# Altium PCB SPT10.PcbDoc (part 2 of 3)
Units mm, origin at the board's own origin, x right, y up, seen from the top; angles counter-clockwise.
Board outline 194 x 91 mm, 4 copper layers (Top Layer, Mid-Layer 8, Mid-Layer 28, Bottom Layer); 266 components, 1 nets, 803 pads, 630 vias.
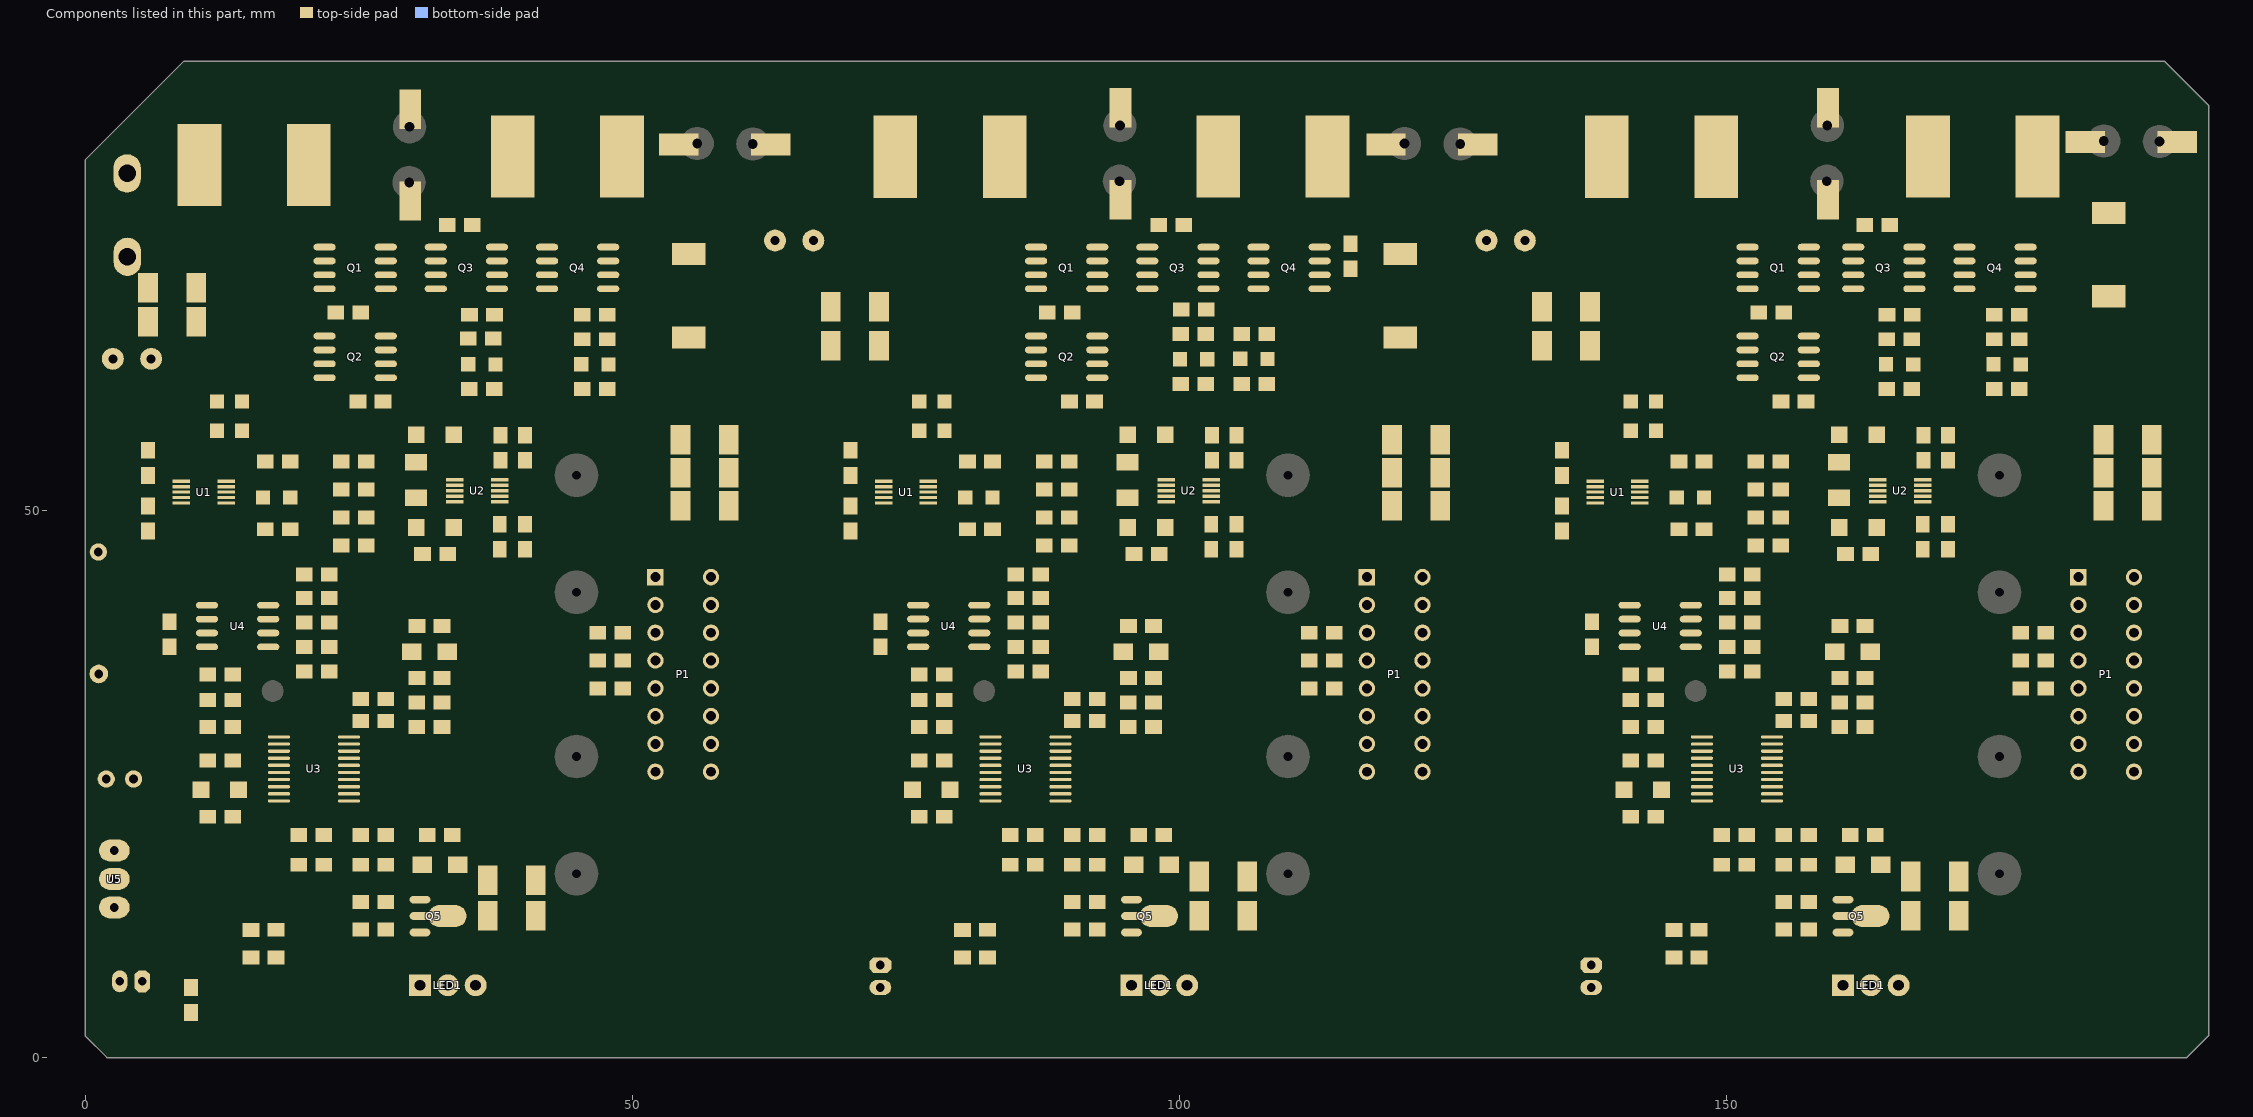
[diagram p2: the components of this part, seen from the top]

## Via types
v1: diameter 1, hole 0.5, Top Layer to Bottom Layer, 627 vias
v2: diameter 1, hole 0.5, Top Layer to Bottom Layer, tented top, 3 vias

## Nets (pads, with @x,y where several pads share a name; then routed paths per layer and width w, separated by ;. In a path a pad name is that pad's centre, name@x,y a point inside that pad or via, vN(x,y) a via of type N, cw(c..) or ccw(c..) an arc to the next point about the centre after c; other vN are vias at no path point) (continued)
copper on no net: | length 4395.1
  Top Layer w0.254: 5.764,64.758 5.764,62.742 6.458,62.742 7.27,61.93 7.27,52.53 7.646,52.154 8.795,52.154 ; 5.765,48.101 6.791,48.101 7.11,48.42 8.38,48.42 ; 5.773,51.657 8.795,51.657 ; 7.709,39.801 v1@7.709,41.549 ; 8.314,50.657 8.795,50.657 ; 8.795,51.157 10.083,51.157 10.57,50.67 10.57,47.56 11.338,46.792 23.414,46.792 ; 8.795,52.657 7.983,52.657 7.9,52.74 7.9,62.55 9.955,64.605 ; 9.44,64.974 9.44,68.53 ; 12.895,51.157 16.38,51.157 ; 12.895,51.657 14.027,51.657 15.25,52.88 18.747,52.88 ; 16.331,51.38 16.4,51.157 16.38,51.157 ; 16.38,51.332 16.38,51.157 ; 17.517,29.291 v1@17.517,30.323 ; 22.31,39.711 21.163,40.858 21.163,43.123 22.31,44.27 ; 30.25,51.15 31.376,52.276 33.79,52.276 ; 30.25,54.37 31.844,52.776 33.79,52.776 ; 30.84,46 31.89,47.05 34.95,47.05 35.69,47.79 35.69,51.11 36.856,52.276 37.89,52.276 ; 33.126,46.001 34.671,46.001 36.28,47.61 36.28,50.32 36.736,50.776 37.89,50.776 ; 33.679,48.43 34.89,48.43 35.14,48.68 35.14,51.276 ; 33.79,51.276 35.14,51.276 ; 33.79,51.776 34.753,51.776 35.3,52.324 35.3,61.069 ; 37.89,51.276 39.694,51.276 40.209,50.761 40.209,48.716 ; 37.89,51.776 39.616,51.776 40.211,52.371 40.211,54.57 ; 37.89,52.776 36.884,52.776 36.55,53.11 36.55,57.497 40.122,61.069 45.412,61.069 ; 39.29,69.74 39.29,60.95 35.94,57.6 35.94,52.076 35.14,51.276 ; 47.535,30.885 48.74,30.885 50.975,28.65 52.11,28.65 ; 68.205,61.835 70.78,61.835 71.5,61.115 71.5,52.46 71.806,52.154 72.955,52.154 ; 69.925,48.101 70.951,48.101 71.3,48.45 71.3,49.97 71.987,50.657 72.955,50.657 ; 69.933,51.657 72.955,51.657 ; 72.58,52.694 72.58,81.876 74.016,83.312 ; 72.677,39.803 v1@72.677,41.551 ; 72.955,51.157 74.243,51.157 74.73,50.67 74.73,47.56 75.498,46.792 87.624,46.792 ; 77.055,51.157 80.54,51.157 ; 77.055,51.657 78.187,51.657 79.41,52.88 82.907,52.88 ; 80.113,48.686 80.54,48.26 ; 80.185,54.445 80.621,54.445 ; 82.517,29.291 v1@82.517,30.323 ; 87.31,39.711 86.163,40.858 86.163,43.123 87.31,44.27 ; 95.25,51.15 96.376,52.276 98.79,52.276 ; 95.25,54.37 96.844,52.776 98.79,52.776 ; 95.84,46 96.89,47.05 99.95,47.05 100.69,47.79 100.69,51.11 101.856,52.276 102.89,52.276 ; 98.126,46.001 99.871,46.001 101.28,47.41 101.28,50.32 101.736,50.776 102.89,50.776 ; 98.679,48.43 99.84,48.43 100.14,48.73 100.14,51.276 ; 98.79,51.276 100.14,51.276 ; 98.79,51.776 99.746,51.776 100.106,52.136 100.106,61.54 ; 102.89,51.276 104.694,51.276 105.209,50.761 105.209,48.716 ; 102.89,51.776 104.616,51.776 105.211,52.371 105.211,54.57 ; 102.89,52.776 101.884,52.776 101.49,53.17 101.49,57.51 104.08,60.1 106.516,60.1 107.958,61.542 ; 103.93,69.74 103.93,60.78 100.96,57.81 100.96,52.096 100.14,51.276 ; 112.535,30.885 113.74,30.885 115.975,28.65 117.11,28.65 ; 133.76,61.99 135.96,61.99 136.5,61.45 136.5,52.46 136.806,52.154 137.955,52.154 ; 134.925,48.101 135.951,48.101 136.3,48.45 136.3,49.97 136.987,50.657 137.955,50.657 ; 134.933,51.657 137.955,51.657 ; 137.58,52.694 137.58,81.876 ; 137.677,39.803 v1@137.677,41.551 ; 137.955,51.157 139.243,51.157 139.73,50.67 139.73,47.56 140.498,46.792 152.624,46.792 ; 140.883,50.657 142.055,50.657 ; 142.055,51.157 145.54,51.157 ; 142.055,51.657 143.187,51.657 144.41,52.88 147.907,52.88 ; 145.113,48.686 145.54,48.26 ; 145.185,54.445 145.621,54.445 ; 147.517,29.291 v1@147.517,30.323 ; 147.907,54.446 148.333,54.02 ; 152.31,39.711 151.163,40.858 151.163,43.123 152.31,44.27 ; 160.25,51.15 161.376,52.276 163.79,52.276 ; 160.25,54.37 161.844,52.776 163.79,52.776 ; 160.84,46 161.89,47.05 164.95,47.05 165.69,47.79 165.69,51.11 166.856,52.276 167.89,52.276 ; 163.126,46.001 164.881,46.001 166.28,47.4 166.28,50.32 166.736,50.776 167.89,50.776 ; 163.679,48.43 164.89,48.43 165.14,48.68 165.14,51.276 ; 163.79,51.276 165.14,51.276 ; 163.79,51.782 164.927,51.782 165.32,52.175 165.32,58.9 164.6,59.62 164.6,61.07 ; 167.89,51.276 169.694,51.276 170.209,50.761 170.209,48.716 ; 167.89,51.776 169.616,51.776 170.211,52.371 170.211,54.57 ; 167.89,52.776 166.884,52.776 166.55,53.11 166.55,57.67 169.95,61.07 174.42,61.07 ; 168.86,60.72 165.92,57.78 165.92,52.056 165.14,51.276 ; 168.87,60.72 168.87,69.74 ; 177.535,30.885 178.74,30.885 180.975,28.65 182.11,28.65
  Top Layer w0.3: 12.062,57.262 11.11,56.31 11.11,52.51 11.463,52.157 12.895,52.157 ; 12.062,59.943 10.52,58.401 10.52,51.86 11.723,50.657 12.895,50.657 ; 13.21,27.42 13.51,27.12 ; 13.24,52.714 13.24,61.2 ; 13.51,22 14.52,22 16.611,24.091 17.009,24.091 ; 13.51,27.341 17.517,27.341 ; 13.51,30.21 15.729,27.991 17.717,27.991 19.351,27.991 21.36,30 ; 14.02,24.741 17.517,24.741 ; 17.14,33.48 15.61,31.95 15.61,29.51 16.479,28.641 17.717,28.641 ; 17.517,25.391 19.479,25.391 v1(19.99,24.88) ; 17.717,23.441 16.881,23.441 16.42,22.98 16.42,14.73 16.926,14.224 25.192,14.224 ; 17.717,26.041 v1(21.429,26.041) ; 17.717,26.691 19.531,26.691 v1(19.91,27.07) ; 19.526,22.367 22.55,25.391 24.117,25.391 ; 24.117,23.441 29.389,23.441 30.61,22.22 v1(30.61,22.29) ; 24.117,24.091 33.949,24.091 v1(35.75,22.29) ; 24.117,24.741 36.001,24.741 v1(37.31,26.05) ; 24.117,26.041 35.271,26.041 42.959,33.729 46.846,33.729 ; 24.117,26.691 34.841,26.691 44.419,36.269 46.844,36.269 ; 24.117,27.341 34.371,27.341 45.839,38.809 46.844,38.809 ; 24.117,27.991 33.951,27.991 46.04,40.08 53.225,40.08 ; 24.117,28.641 28.751,28.641 30.32,30.21 ; 24.117,29.291 25.091,29.291 25.19,29.39 25.19,30.74 ; 53.225,40.09 57.117,36.198 ; 76.222,57.262 75.27,56.31 75.27,52.51 75.623,52.157 77.055,52.157 ; 76.222,59.943 74.68,58.401 74.68,51.86 75.883,50.657 77.055,50.657 ; 77.4,52.714 77.4,61.36 ; 78.51,22 79.52,22 81.611,24.091 82.009,24.091 ; 78.51,27.341 82.517,27.341 ; 78.51,30.21 80.729,27.991 82.717,27.991 84.271,27.991 ; 79.02,24.741 82.517,24.741 ; 81.229,27.341 82.717,27.341 ; 82.14,33.48 80.61,31.95 80.61,29.51 81.479,28.641 82.717,28.641 ; 82.517,25.391 84.479,25.391 v1(84.99,24.88) ; 82.717,23.441 81.881,23.441 81.42,22.98 81.42,14.68 81.876,14.224 90.192,14.224 ; 82.717,26.041 v1(86.429,26.041) ; 82.717,26.691 84.531,26.691 v1(84.91,27.07) ; 84.351,27.991 86.36,30 ; 84.526,22.367 87.55,25.391 89.117,25.391 ; 89.117,23.441 94.389,23.441 v1@95.61,22.22 ; 89.117,24.091 98.949,24.091 v1(100.75,22.29) ; 89.117,24.741 101.001,24.741 v1(102.31,26.05) ; 89.117,26.041 100.271,26.041 107.959,33.729 111.846,33.729 ; 89.117,26.691 99.841,26.691 109.419,36.269 111.846,36.269 ; 89.117,27.341 99.371,27.341 110.839,38.809 112.069,38.809 ; 89.117,27.991 98.961,27.991 111.06,40.09 118.225,40.09 122.118,36.198 ; 89.117,28.641 93.751,28.641 95.32,30.21 ; 89.117,29.291 90.091,29.291 90.19,29.39 90.19,30.74 ; 140.883,50.657 139.68,51.86 139.68,58.401 141.222,59.943 ; 141.222,57.262 140.27,56.31 140.27,52.51 140.623,52.157 142.055,52.157 ; 142.4,52.714 142.4,61.36 ; 143.51,22 144.52,22 146.611,24.091 147.009,24.091 ; 143.51,27.341 147.517,27.341 ; 143.51,30.21 145.729,27.991 147.717,27.991 149.271,27.991 ; 144.02,24.741 147.517,24.741 ; 147.14,33.48 145.62,31.96 145.62,31.94 145.61,31.93 145.61,29.51 146.479,28.641 147.717,28.641 ; 147.517,25.391 149.479,25.391 v1(149.99,24.88) ; 147.717,23.441 146.881,23.441 146.49,23.05 146.49,14.75 147.016,14.224 155.192,14.224 ; 147.717,26.041 v1(151.429,26.041) ; 147.717,26.691 149.531,26.691 v1(149.91,27.07) ; 149.351,27.991 151.36,30 ; 149.526,22.367 152.55,25.391 154.117,25.391 ; 154.117,23.441 159.389,23.441 v1@160.61,22.22 ; 154.117,24.091 163.949,24.091 v1(165.75,22.29) ; 154.117,24.741 166.001,24.741 v1(167.31,26.05) ; 154.117,26.041 165.271,26.041 172.959,33.729 176.846,33.729 ; 154.117,26.691 164.841,26.691 174.419,36.269 176.846,36.269 ; 154.117,27.341 164.371,27.341 175.839,38.809 177.069,38.809 ; 154.117,27.991 163.951,27.991 176.03,40.07 183.225,40.07 ; 154.117,28.641 158.751,28.641 160.32,30.21 ; 154.117,29.291 155.091,29.291 155.19,29.39 155.19,30.74 ; 183.225,40.09 187.118,36.198
  Top Layer w0.35: 21.36,30 21.36,33.32 22.03,33.99 24.61,33.99 27.7,37.08 29.84,37.08 ; 86.36,30 86.36,33.32 87.03,33.99 89.61,33.99 92.7,37.08 94.84,37.08 ; 151.36,30 151.36,33.34 152.01,33.99 154.61,33.99 157.7,37.08 159.84,37.08
  Top Layer w0.4: 13.24,61.2 13.86,61.82 16.687,61.82 ; 13.29,54.445 16.461,54.445 ; 77.4,61.36 77.86,61.82 85.367,61.82 ; 77.45,54.445 80.621,54.445 ; 142.4,61.36 142.86,61.82 146.167,61.82 ; 142.45,54.445 145.621,54.445
  Top Layer w0.5: 3.95,13.81 5.626,12.134 5.626,6.96 7.71,6.96 23.85,6.96 27.2,3.61 60.11,3.61 60.42,3.92 60.42,29.7 58.93,31.19 57.19,31.19 ; 5.764,55.467 5.764,62.742 ; 7.71,37.515 11.146,37.515 ; 7.771,34.989 11.224,34.989 ; v1(9.01,24.48) 8.813,24.48 8.812,24.481 10.56,24.481 ; v1(9.41,32.68) 11.224,32.679 ; v1(9.445,22.03) 11.193,22.03 ; v1(9.445,27.15) 11.193,27.15 ; v1(9.445,30.24) v1@9.476,30.209 ; 13.51,30.21 13.51,34.99 ; 14.348,57.404 v1@16.356,57.404 ; 14.348,59.944 25.257,59.944 ; 15.19,11.695 v1(15.19,16.23) ; 16.38,48.26 16.38,51.157 ; 16.702,38.787 19.081,38.787 20.024,39.73 ; 16.702,40.057 18.111,40.057 20.024,41.97 ; 16.71,41.325 v1(16.71,42.56) 16.71,41.335 ; 16.734,37.515 19.85,37.515 ; 17.45,9.145 32.3,9.145 33.15,8.295 33.15,6.604 ; 17.45,11.67 v1(20.61,11.67) ; 18.666,48.261 v1@20.599,48.261 ; 18.747,51.446 18.747,52.88 18.747,54.446 ; 19.526,17.615 19.526,22.367 ; v1(20.024,34) 20.024,37.342 ; 20.024,39.71 22.31,37.424 22.31,37.69 22.31,37.343 22.31,35.25 ; 20.024,41.97 20.024,44.269 ; 21.811,17.616 25.187,17.616 ; 21.811,20.317 v2(21.811,21.801) ; 21.89,65.913 21.89,64.643 21.89,63.373 21.89,62.103 20.227,62.103 19.81,62.52 19.81,71.43 20.389,72.009 21.89,72.009 21.89,73.279 21.89,74.549 21.89,82.97 ; 21.89,70.231 24.279,70.231 25.192,69.318 25.192,68.072 ; 22.31,41.971 23.327,41.971 24.099,42.743 40.96,42.743 42.244,44.028 42.244,57.354 43.43,58.54 55.57,58.54 56.23,57.88 56.23,56.39 55.774,55.934 54.405,55.934 ; 22.31,44.27 23.327,44.27 24.099,43.497 40.647,43.497 41.49,44.34 41.49,57.666 43.118,59.294 55.882,59.294 56.763,58.413 56.984,58.192 56.984,56.386 57.436,55.934 58.805,55.934 ; 24.937,59.944 24.937,65.397 25.453,65.913 27.478,65.913 ; v1(25.07,22.16) 27.09,22.16 27.478,21.772 27.478,20.317 ; 25.132,11.753 27.418,14.039 ; 25.19,30.74 25.19,32.769 ; 25.192,17.61 25.192,20.316 ; 25.7,46.793 25.7,49.333 ; 25.7,49.334 25.7,51.894 ; 25.7,54.445 25.7,55.95 26.646,56.896 30.272,56.896 32.47,59.094 32.47,72.38 ; 25.76,48 v1(27.257,48) ; v1(27.47,29.7) v1@27.476,29.706 ; 27.478,11.684 27.735,11.427 v1(28.99,11.427) 30.603,11.427 ; 27.478,17.611 30.759,17.611 31.256,18.108 31.256,20.316 ; 27.478,62.103 27.478,63.373 27.478,64.643 ; 27.68,14.427 30.603,14.427 ; v1(29.03,46) 30.84,46 ; 29.84,37.08 30.324,37.564 30.324,39.429 ; 30.323,30.748 30.326,30.75 30.326,34.689 ; 32.606,30.211 32.606,32.451 ; 32.61,34.69 36.012,34.69 v1(37.521,33.181) ; 32.61,39.43 42.13,39.43 45.046,42.346 46.042,41.35 52.11,41.35 ; 32.626,31.31 v1(34.64,31.31) ; 33.09,37.08 v1(34.92,37.08) ; 33.542,20.317 35.967,20.317 38.78,23.13 38.78,28.37 40.98,30.57 42.74,30.57 44.9,28.41 44.9,29.762 46.328,31.19 ; v1@34.05,15.76 34.05,17.54 ; 35.094,61.069 35.094,63.254 ; 35.098,65.619 35.098,73.688 35.451,74.041 37.638,74.041 ; v1(36.14,46) 37.461,46 37.891,46.43 ; 37.38,61.07 37.38,65.62 ; 37.89,48.716 40.209,48.716 ; 37.91,54.57 40.21,54.57 ; 37.968,56.855 37.968,57.619 v1(38.469,58.12) ; v1(40.2,45.15) 40.2,46.43 ; 40.309,56.956 v1(40.309,58.62) ; 45.27,65.619 45.27,73.65 45.661,74.041 47.798,74.041 ; 45.339,61.143 45.339,63.327 ; 47.698,61.07 47.698,65.62 ; 49.13,36.27 52.11,36.27 ; 49.13,38.81 52.11,38.81 ; 49.132,33.73 52.11,33.73 ; 57.19,33.73 59.47,33.73 61.87,31.33 v1@61.87,10.63 ; 57.19,38.784 58.766,38.784 62.99,34.56 ; 61.28,36.27 62.99,34.56 ; v1(62.99,8.44) 62.99,34.56 ; v1@66.824,73.152 68.18,71.796 68.18,65.024 ; 68.567,61.81 68.567,59.178 69.924,57.821 69.924,55.467 ; 72.66,8.44 76.82,8.44 81.518,3.742 104.212,3.742 107.76,7.29 124.747,7.29 125.6,8.143 125.6,29.86 124.27,31.19 122.19,31.19 ; 72.678,37.517 76.114,37.517 ; 72.771,34.989 76.224,34.989 ; v1(73.98,24.48) 73.813,24.48 73.812,24.481 75.56,24.481 ; v1(74.445,22.03) 76.193,22.03 ; v1(74.445,27.15) 76.193,27.15 ; v1(74.445,30.24) v1@74.476,30.209 ; 76.114,41.327 76.122,41.335 ; 78.508,57.404 v1@80.516,57.404 ; 78.508,59.944 89.937,59.944 89.937,65.397 90.453,65.913 92.478,65.913 ; 78.51,30.21 78.51,34.99 ; 80.19,11.695 v1(80.19,16.23) ; 80.54,48.26 80.54,51.157 ; 81.702,38.787 84.081,38.787 85.024,39.73 ; 81.702,40.057 83.111,40.057 85.024,41.97 ; 81.71,41.335 v1(81.71,42.56) ; 81.734,37.515 84.85,37.515 ; 82.45,9.145 97.065,9.145 98.15,8.06 98.15,6.604 ; 82.45,11.67 v1(85.61,11.67) ; 82.826,48.261 v1@84.759,48.261 ; 82.907,51.446 82.907,54.446 ; 84.016,83.312 86.548,83.312 ; 84.526,17.615 84.526,22.367 ; 84.81,71.43 85.389,72.009 86.89,72.009 86.89,73.279 86.89,74.549 86.89,82.97 ; v1(85.024,34) 85.024,37.342 ; 85.024,39.629 87.31,37.343 87.31,35.25 ; 85.024,41.97 85.024,44.269 ; 85.227,62.103 86.89,62.103 86.89,63.373 86.89,64.643 86.89,65.913 ; 86.811,17.616 90.187,17.616 ; 86.811,20.317 v2(86.811,21.801) ; 86.89,70.231 89.279,70.231 90.192,69.318 90.192,68.072 ; 87.31,41.971 88.327,41.971 89.099,42.743 105.96,42.743 107.244,44.028 107.244,57.354 108.43,58.54 120.57,58.54 121.23,57.88 121.23,56.39 120.774,55.934 119.405,55.934 ; 87.31,44.27 88.327,44.27 89.099,43.497 105.648,43.497 106.49,44.34 106.49,57.666 108.118,59.294 120.882,59.294 121.984,58.192 121.984,56.386 122.436,55.934 123.805,55.934 ; 89.91,46.793 89.91,49.333 ; 89.91,49.345 89.91,51.894 ; 89.91,54.445 89.91,55.95 90.856,56.896 95.272,56.896 97.47,59.094 97.47,72.38 ; 89.97,48 v1(91.467,48) ; v1(90.07,22.16) 92.09,22.16 92.478,21.772 92.478,20.317 ; 90.132,11.753 92.418,14.039 ; 90.19,30.74 90.19,32.769 ; 90.192,17.61 90.192,20.316 ; 92.478,11.684 92.735,11.427 v1(93.99,11.427) 95.603,11.427 ; 92.478,17.611 95.759,17.611 ; 92.478,62.103 92.478,63.373 92.478,64.643 ; 92.68,14.427 95.603,14.427 ; 92.86,79.27 92.478,78.888 92.478,70.739 97.05,70.739 97.05,74.549 ; v1(94.03,46) 95.84,46 ; 94.84,37.08 95.324,37.564 95.324,39.429 ; 95.326,30.75 95.326,34.689 ; 96.256,18.108 96.256,20.316 ; 97.606,30.211 97.606,32.451 ; 97.61,34.69 101.012,34.69 v1(102.521,33.181) ; 97.61,39.43 107.13,39.43 110.046,42.346 111.042,41.35 117.11,41.35 ; 97.626,31.31 v1(99.64,31.31) ; 98.09,37.08 v1(99.92,37.08) ; 98.542,20.317 100.867,20.317 103.78,23.23 103.78,28.37 105.98,30.57 107.74,30.57 109.9,28.41 ; v1@99.05,15.76 99.05,17.54 ; 100.098,66.09 100.098,73.688 100.451,74.041 102.638,74.041 ; 100.106,61.54 100.106,63.724 ; v1(101.55,46) 102.461,46 102.891,46.43 ; 102.392,61.541 102.392,66.091 ; 102.89,48.716 105.209,48.716 ; 102.91,54.57 105.21,54.57 ; 102.968,56.855 102.968,57.619 v1(103.469,58.12) ; v1(105.13,27.32) 105.13,21.722 110.01,16.842 ; v1(105.2,44.91) 105.2,46.43 ; 105.309,56.956 v1(105.309,58.62) ; 105.672,61.541 105.672,66.09 ; 107.958,66.091 110.24,68.373 110.24,73.59 110.691,74.041 112.794,74.041 115.304,74.041 115.609,74.346 ; 108.031,61.615 108.031,63.826 ; 109.9,27.8 109.9,28.41 ; 111.158,31.19 109.9,29.932 109.9,28.41 ; 114.132,33.73 117.11,33.73 ; 114.132,36.27 117.11,36.27 ; 114.132,38.81 117.11,38.81 ; 122.19,33.73 124.47,33.73 126.87,31.33 v1(126.87,10.63) ; 122.19,38.784 123.766,38.784 127.99,34.56 v1(127.99,8.99) ; v1@131.824,73.152 133.18,71.796 133.18,65.024 ; 133.567,61.33 133.567,59.293 134.924,57.936 134.924,55.467 ; 137.678,37.517 141.114,37.517 ; 137.771,34.989 141.224,34.989 ; v1(139.07,24.48) 138.813,24.48 138.812,24.481 140.56,24.481 ; v1(139.445,22.03) 141.193,22.03 ; v1(139.445,27.15) 141.193,27.15 ; v1(139.445,30.24) v1@139.476,30.209 ; 141.518,7.738 147.516,1.74 190.1,1.74 190.75,2.39 190.75,29.585 189.145,31.19 187.19,31.19 ; 143.508,57.404 v1@145.516,57.404 ; 143.508,59.944 154.937,59.944 154.937,65.397 155.453,65.913 157.478,65.913 ; 143.51,30.21 143.51,34.99 ; 145.19,11.695 v1(145.19,16.23) ; 145.54,48.26 145.54,51.157 ; 146.702,38.787 149.101,38.787 150.024,39.71 ; 146.702,40.057 148.111,40.057 150.024,41.97 ; 146.702,41.327 145.027,41.327 145.035,41.335 146.71,41.335 v1(146.71,42.56) ; 146.734,37.515 149.85,37.515 ; 147.45,9.145 162.15,9.145 163.15,8.145 163.15,6.604 ; 147.45,11.67 v1(150.61,11.67) ; 147.826,48.261 v1@149.759,48.261 ; 147.907,51.446 147.907,54.446 ; 149.526,17.615 149.526,22.367 ; 150.024,39.629 152.31,37.343 152.31,35.25 ; v1(150.024,34) 150.024,37.342 ; 150.024,41.97 150.024,44.269 ; 151.811,17.616 155.187,17.616 ; 151.811,20.317 v2(151.811,21.801) ; 151.89,65.913 151.89,64.643 151.89,63.373 151.89,62.103 150.227,62.103 149.81,62.52 149.81,71.43 150.389,72.009 151.89,72.009 151.89,73.279 151.89,74.549 151.89,82.97 ; 151.89,70.231 154.279,70.231 155.192,69.318 155.192,68.072 ; 152.31,41.971 153.327,41.971 154.099,42.743 170.96,42.743 172.244,44.028 172.244,57.354 173.43,58.54 185.57,58.54 186.23,57.88 186.23,56.39 185.774,55.934 184.405,55.934 ; 152.31,44.27 153.327,44.27 154.099,43.497 170.648,43.497 171.49,44.34 171.49,57.666 173.118,59.294 185.882,59.294 186.984,58.192 186.984,56.386 187.436,55.934 188.805,55.934 ; 154.91,46.793 154.91,49.333 ; 154.91,49.345 154.91,51.894 ; 154.91,54.445 154.91,55.95 155.856,56.896 160.272,56.896 162.47,59.094 162.47,72.38 ; 154.97,48 v1(156.467,48) ; v1(155.07,22.16) 157.09,22.16 157.478,21.772 157.478,20.317 ; 155.132,11.753 157.418,14.039 ; 155.19,30.74 155.19,32.769 ; 155.192,17.61 155.192,20.316 ; 157.478,11.684 157.735,11.427 v1(158.99,11.427) 160.603,11.427 ; 157.478,17.611 160.759,17.611 ; 157.478,62.103 157.478,63.373 157.478,64.643 ; 157.68,14.427 160.603,14.427 ; 157.86,79.27 157.478,78.888 157.478,70.739 162.05,70.739 162.05,74.549 ; v1(159.03,46) 160.84,46 ; 159.84,37.08 160.324,37.564 160.324,39.429 ; 160.326,30.75 160.326,34.689 ; 161.256,18.108 161.256,20.316 ; 162.606,30.211 162.606,32.451 ; 162.61,34.69 166.012,34.69 v1(167.521,33.181) ; 162.61,39.43 172.13,39.43 175.046,42.346 176.042,41.35 182.11,41.35 ; 162.626,31.31 v1(164.64,31.31) ; 163.09,37.08 v1(164.92,37.08) ; 163.542,20.317 166.067,20.317 168.78,23.03 168.78,28.37 170.98,30.57 172.74,30.57 174.9,28.41 ; v1@164.05,15.76 164.05,17.54 ; 164.59,65.62 164.59,73.41 165.221,74.041 167.638,74.041 ; 164.6,61.07 164.6,63.254 ; v1(166.55,46) 167.461,46 167.891,46.43 ; 166.886,61.071 166.886,65.621 ; 167.91,54.57 170.21,54.57 ; 167.968,56.855 167.968,57.619 v1(168.469,58.12) ; 170.13,21.362 v1(170.13,27.32) ; v1(170.2,44.9) 170.2,46.43 ; 170.309,56.956 v1(170.309,58.62) ; 174.347,61.143 174.347,63.328 ; 174.396,65.62 174.396,73.306 175.131,74.041 177.798,74.041 ; 174.9,27.8 174.9,28.41 ; 176.398,31.19 174.9,29.692 174.9,28.41 ; 176.706,61.071 176.706,65.621 ; 177.798,70.739 177.798,72.009 ; 179.132,33.73 182.11,33.73 ; 179.132,36.27 182.11,36.27 ; 179.132,38.81 182.11,38.81 ; 187.19,33.73 189.47,33.73 191.87,31.33 v1(191.87,10.63) ; 187.19,38.784 188.766,38.784 192.99,34.56 ; 191.28,36.27 192.99,34.56 ; v1(192.18,8.954) 192.99,9.764 192.99,34.56
  Top Layer w0.75: 7.71,6.53 7.71,6.96 7.71,37.515 ; 72.678,8.44 72.678,37.517 ; 137.678,8.446 137.678,37.517
  Top Layer w0.8: 13.21,27.42 v1(13.21,28.39) ; 23.414,46.793 23.414,51.893 23.414,54.444 ; 78.21,27.42 v1(78.21,28.39) ; 87.624,46.793 87.624,51.893 87.624,54.444 ; 143.21,27.42 v1(143.21,28.39) ; 152.624,46.793 152.624,51.893 152.624,54.444
  Top Layer w1: 5.765,50.388 5.765,53.181 ; v1@27.476,29.706 27.476,30.741 ; 27.53,32.824 v1(27.53,34) ; 30.252,48.43 30.252,51.15 ; 30.252,54.37 30.252,56.896 ; 33.103,12.927 36.771,12.927 ; 33.701,56.896 v1(33.701,58.661) ; 69.925,50.388 69.925,53.181 ; v1@92.476,29.706 92.476,30.741 ; 92.53,32.824 v1(92.53,34) ; 95.252,48.43 95.252,51.15 ; 95.252,54.37 95.252,56.896 ; 98.103,12.927 101.771,12.927 ; 98.701,56.896 v1(98.701,58.661) ; 134.925,50.388 134.925,53.181 ; v1@157.476,29.706 157.476,30.741 ; 157.53,32.824 v1(157.53,34) ; 160.252,48.43 160.252,51.15 ; 160.252,54.37 160.252,56.896 ; 163.103,12.927 166.771,12.927 ; 163.701,56.896 v1(163.701,58.661)
  Bottom Layer w0.5: v1@13.21,28.58 13.21,10.577 15.067,8.72 24.15,8.72 25.36,7.51 25.36,4.4 27.18,2.58 39.09,2.58 44.95,8.44 v1(62.99,8.44) ; v1(15.19,16.23) 15.19,22.16 15.78,22.75 20.66,22.75 21.429,23.519 v1(21.429,26.041) ; v1(16.42,57.34) 23.38,57.34 25.2,59.16 v1(25.2,69.31) ; v1(17.49,30.35) 23.94,30.35 25.07,29.22 v1(25.07,22.16) ; v1@19.858,27.07 16.47,27.07 15.56,27.98 15.56,35.193 16.209,35.842 38.202,35.842 40.21,37.85 v1@40.21,45.15 ; v1(20.024,34) v1(27.53,34) ; v1(20.61,11.67) 25.91,11.67 27.87,13.63 27.87,24.08 28.49,24.7 48.12,24.7 48.95,25.53 48.95,29.41 50.729,31.189 52.11,31.189 ; 26.22,9.95 26.22,5.325 28.065,3.48 38.6,3.48 45.75,10.63 v1(61.89,10.63) ; 30.61,6.604 v1(30.61,22.29) ; 35.75,6.664 v1(35.75,22.29) ; v1(37.31,26.05) 40.63,26.05 41.34,26.76 41.34,57.589 v1(40.309,58.62) ; v1(37.521,33.181) 40.13,30.572 v1(40.13,27.32) ; 44.9,27.5 44.9,29.3 46.79,31.19 ; 44.9,42.5 46.05,41.35 52.11,41.35 ; v1@78.21,28.58 78.21,10.577 80.067,8.72 89.15,8.72 90.36,7.51 90.36,4.4 92.18,2.58 ; v1(80.19,16.23) 80.19,22.16 80.78,22.75 85.66,22.75 86.429,23.519 v1(86.429,26.041) ; v1(80.58,57.34) 88.38,57.34 90.2,59.16 v1(90.2,69.31) ; v1(82.49,30.35) 88.94,30.35 90.07,29.22 v1(90.07,22.16) ; v1(84.91,27.07) 81.47,27.07 80.56,27.98 80.56,35.193 81.209,35.842 103.202,35.842 105.21,37.85 v1@105.21,45.15 ; v1(85.024,34) v1(92.53,34) ; v1(85.61,11.67) 90.91,11.67 92.87,13.63 92.87,24.08 93.49,24.7 113.12,24.7 113.95,25.53 113.95,29.41 115.729,31.189 117.11,31.189 ; 91.22,9.95 91.22,4.68 92.47,3.43 103.18,3.43 109.46,9.71 125.95,9.71 v1(126.87,10.63) ; 92.24,2.52 103.52,2.52 109.954,8.954 v1@127.87,8.954 ; 95.61,6.604 v1@95.61,22.05 ; 100.75,6.664 v1@100.75,22.32 ; v1(102.31,26.05) 105.63,26.05 106.34,26.76 106.34,57.589 v1(105.309,58.62) ; v1(102.521,33.181) 105.13,30.572 v1(105.13,27.32) ; 109.9,27.5 109.9,29.254 111.837,31.19 ; 109.9,42.5 111.05,41.35 117.11,41.35 ; v1(143.21,28.39) 143.21,10.577 145.067,8.72 154.15,8.72 155.36,7.51 155.36,4.4 157.495,2.265 169.07,2.265 175.758,8.954 v1(192.18,8.954) ; v1(145.19,16.23) 145.19,22.16 145.78,22.75 150.66,22.75 151.429,23.519 v1(151.429,26.041) ; v1(145.58,57.34) 153.34,57.34 153.38,57.34 155.2,59.16 v1(155.2,69.31) ; v1(147.49,30.35) 153.94,30.35 155.07,29.22 v1(155.07,22.16) ; v1(149.91,27.07) 146.22,27.07 145.56,27.73 145.56,34.943 146.209,35.592 168.202,35.592 170.21,37.6 v1@170.21,44.9 ; v1(150.024,34) v1(157.53,34) ; v1(150.61,11.67) 155.91,11.67 157.87,13.63 157.87,24.08 158.49,24.7 178.12,24.7 178.95,25.53 178.95,29.41 180.729,31.189 182.11,31.189 ; 156.22,9.95 156.22,4.69 157.895,3.015 168.475,3.015 175.17,9.71 190.95,9.71 v1(191.87,10.63) ; 160.61,6.604 v1(160.61,22.29) ; 165.69,6.604 165.75,6.664 v1@165.75,22.62 ; v1(167.31,26.05) 170.63,26.05 171.34,26.76 171.34,57.589 v1(170.309,58.62) ; v1(167.521,33.181) 170.13,30.572 v1(170.13,27.32) ; 174.9,27.5 174.9,28.78 177.31,31.19 ; 174.9,42.5 176.05,41.35 182.11,41.35
  other v1: 34.06,15.76 99.06,15.76 164.06,15.76 95.61,22.29 92.47,29.7 157.47,29.7 74.41,32.68 139.41,32.68 7.74,41.58 72.708,41.582 137.708,41.582 8.39,47.755 137.39,47.895 72.44,48.115 20.63,48.23 84.79,48.23 149.79,48.23 49.808,50.088 51.068,50.088 114.808,50.088 116.068,50.088 179.808,50.088 181.068,50.088 49.75,51.299 51.01,51.299 114.75,51.299 116.01,51.299 179.75,51.299 181.01,51.299 49.75,52.51 50.952,52.51 114.75,52.51 115.952,52.51 179.75,52.51 180.952,52.51 49.75,53.721 50.952,53.721 114.75,53.721 115.952,53.721 179.75,53.721 180.952,53.721 49.75,54.931 50.952,54.932 114.75,54.931 115.952,54.932 179.75,54.931 180.952,54.932 190.474,59.16 191.94,59.16 190.474,60.93 191.94,60.93 180.68,61.048 181.891,61.048 183.102,61.048 184.312,61.048 185.523,61.048 53.468,61.72 54.679,61.72 55.889,61.72 57.1,61.72 1.02,61.81 30.013,61.892 95.013,61.892 160.013,61.892 180.68,62.25 181.891,62.25 183.101,62.25 184.312,62.25 185.523,62.25 118.401,62.67 119.611,62.67 120.822,62.67 122.033,62.67 60.5,62.75 61.967,62.75 125.5,62.75 126.967,62.75 30.013,63.162 95.013,63.162 160.013,63.162 1.02,63.358 53.468,63.44 54.679,63.44 55.889,63.44 57.1,63.44 118.399,63.94 119.61,63.94 120.821,63.94 122.031,63.94 74.405,64.242 139.37,64.242 30.013,64.305 95.013,64.305 160.013,64.305 66.412,64.442 131.377,64.442 60.5,64.52 61.967,64.52 125.5,64.52 126.967,64.52 1.02,64.906 74.405,65.742 139.37,65.742 66.412,65.942 131.377,65.942 146.78,66.082 148.266,66.082 3.88,66.415 11.82,66.415 1.02,66.454 146.78,67.472 148.266,67.472 66.412,67.8 131.377,67.8 74.405,67.842 139.37,67.842 3.88,67.86 11.82,67.86 1.02,68.002 81.78,68.862 83.266,68.862 146.78,68.862 148.266,68.862 66.412,69.142 131.377,69.142 16.513,69.224 18,69.224 74.405,69.342 139.37,69.342 1.02,69.55 3.88,69.72 11.82,69.72 169.967,69.767 40.263,69.992 50.153,70.012 179.403,70.012 29.71,70.042 94.71,70.042 159.71,70.042 81.78,70.252 83.266,70.252 114.32,70.25 146.78,70.252 148.266,70.252 16.513,70.614 18,70.614 3.88,71.02 11.82,71.02 1.02,71.098 105.24,71.102 169.967,71.19 50.153,71.282 179.403,71.282 40.24,71.32 29.71,71.395 94.71,71.395 159.71,71.395 114.32,71.52 81.78,71.642 83.266,71.642 146.78,71.642 148.266,71.642 16.513,72.004 18,72.004 50.153,72.425 179.403,72.425 10.098,72.475 11.285,72.475 12.473,72.475 105.223,72.474 169.967,72.613 1.02,72.646 114.32,72.663 40.223,72.692 29.71,72.747 94.71,72.747 159.71,72.747 81.8,73 82.988,73 84.175,73 85.363,73 146.8,73 147.988,73 149.176,73 150.363,73 72.25,73.021 73.438,73.021 74.625,73.021 75.813,73.021 137.25,73.021 138.438,73.021 139.625,73.021 140.813,73.021 66.768,73.242 68.11,73.242 131.768,73.242 133.11,73.242 181.77,73.26 183.16,73.26 184.55,73.26 185.94,73.26 187.33,73.26 16.513,73.394 18,73.394 10.1,73.81 11.288,73.81 12.475,73.81 105.24,74.042 169.967,74.035 29.71,74.1 94.71,74.1 159.71,74.1 1.02,74.194 40.24,74.26 72.222,74.428 73.41,74.428 74.598,74.428 75.785,74.428 81.772,74.407 82.96,74.407 84.148,74.407 85.336,74.407 137.222,74.428 138.41,74.428 139.598,74.428 140.785,74.428 146.772,74.407 147.96,74.407 149.148,74.407 150.336,74.407 68.11,74.642 133.11,74.642 181.77,74.746 183.16,74.746 184.55,74.746 185.94,74.746 187.33,74.746 16.513,74.784 18,74.784 10.102,75.145 11.29,75.145 12.478,75.145 51.387,75.5 52.777,75.5 54.167,75.5 55.557,75.5 56.947,75.5 117.987,75.5 119.377,75.5 120.767,75.5 122.157,75.5 1.02,75.742 166.96,75.79 168.35,75.79 169.74,75.79 171.13,75.79 172.52,75.79 81.745,75.814 82.932,75.814 84.12,75.814 85.308,75.814 146.745,75.814 147.932,75.814 149.12,75.814 150.308,75.814 72.195,75.835 73.382,75.835 74.57,75.835 75.758,75.835 137.195,75.835 138.382,75.835 139.57,75.835 140.758,75.835 37.45,76.104 38.84,76.104 40.23,76.104 41.62,76.104 43.01,76.104 102.067,76.124 103.457,76.124 104.847,76.124 106.237,76.124 107.627,76.124 10.105,76.48 11.292,76.48 12.48,76.48 27.32,76.542 28.48,76.542 92.32,76.542 93.48,76.542 157.32,76.542 158.48,76.542 51.387,76.986 52.777,76.986 54.167,76.986 55.557,76.986 56.947,76.986 117.987,76.986 119.377,76.986 120.767,76.986 122.157,76.986 81.717,77.22 82.905,77.22 84.092,77.22 85.28,77.22 146.717,77.22 147.905,77.22 149.092,77.22 150.28,77.22 72.167,77.242 73.355,77.242 74.542,77.242 75.73,77.242 137.167,77.242 137.167,77.242 138.355,77.242 138.355,77.242 139.542,77.242 139.542,77.242 140.73,77.242 140.73,77.242 1.02,77.29 166.96,77.276 168.35,77.276 169.74,77.276 171.13,77.276 172.52,77.276 37.45,77.59 38.84,77.59 40.23,77.59 41.62,77.59 43.01,77.59 102.067,77.61 103.457,77.61 104.847,77.61 106.237,77.61 107.627,77.61 165.364,78.592 171.225,78.59 172.515,78.59 175.455,78.585 181.315,78.585 182.565,78.585 116.475,78.75 117.665,78.75 46.045,78.79 52.105,78.79 53.345,78.79 35.864,78.86 42.085,78.86 43.335,78.86 100.484,78.95 106.76,78.95 108.25,78.95 15.98,79.435 17.466,79.435 23.415,79.435 80.855,79.435 87,79.435 88.166,79.434 145.845,79.435 151.68,79.434 153.166,79.434 11.559,79.44 13.045,79.44 70.655,79.44 72.141,79.44 76.655,79.44 141.655,79.44 135.5,79.53 136.986,79.53 165.364,79.982 171.225,79.98 172.515,79.98 175.455,79.975 181.315,79.975 182.565,79.975 116.475,80.14 117.665,80.14 46.045,80.18 52.105,80.18 53.345,80.18 35.864,80.25 42.085,80.25 43.335,80.25 100.484,80.34 106.76,80.34 108.25,80.34 11.559,80.83 13.045,80.83 15.98,80.825 17.466,80.825 23.415,80.825 70.655,80.83 72.141,80.83 76.655,80.83 80.855,80.825 87,80.825 88.166,80.824 141.655,80.83 145.845,80.825 151.68,80.824 153.166,80.824 135.5,80.92 136.986,80.92 175.455,81.365 181.315,81.365 182.565,81.365 165.364,81.372 171.225,81.37 172.515,81.37 116.475,81.53 117.665,81.53 46.045,81.57 52.105,81.57 53.345,81.57 35.864,81.64 42.085,81.64 43.335,81.64 100.484,81.73 106.76,81.73 108.25,81.73 11.559,82.22 13.045,82.22 15.98,82.215 17.466,82.215 23.415,82.215 70.655,82.22 72.141,82.22 80.855,82.215 87,82.215 88.166,82.214 145.845,82.215 151.68,82.214 153.166,82.214 76.625,82.28 141.625,82.28 135.5,82.31 136.986,82.31 165.364,82.762 171.225,82.76 172.515,82.76 175.455,82.755 181.315,82.755 182.565,82.755 116.475,82.92 117.665,82.92 46.045,82.96 52.105,82.96 53.345,82.96 35.864,83.03 42.085,83.03 43.335,83.03 100.484,83.12 106.76,83.12 108.25,83.12 11.559,83.61 13.045,83.61 15.98,83.605 17.466,83.605 23.415,83.605 70.655,83.61 72.141,83.61 76.655,83.61 80.855,83.605 87,83.605 88.166,83.604 141.655,83.61 145.845,83.605 151.68,83.604 153.166,83.604 135.5,83.7 136.986,83.7 165.364,84.152 171.225,84.15 172.515,84.15 175.455,84.145 181.315,84.145 182.565,84.145 116.475,84.31 117.665,84.31 46.045,84.35 52.105,84.35 53.345,84.35 35.864,84.42 42.085,84.42 43.335,84.42 100.484,84.51 106.76,84.51 108.25,84.51 15.98,84.995 17.466,84.995 23.415,84.995 80.855,84.995 87,84.995 88.166,84.994 145.845,84.995 151.68,84.994 153.166,84.994 11.559,85 13.045,85 70.655,85 72.141,85 76.655,85 141.655,85 135.5,85.09 136.986,85.09 165.364,85.542 171.225,85.54 172.515,85.54 175.455,85.535 181.315,85.535 182.565,85.535 116.475,85.7 117.665,85.7 46.045,85.74 52.105,85.74 53.345,85.74 35.864,85.81 42.085,85.81 43.335,85.81 100.484,85.9 106.76,85.9 108.25,85.9

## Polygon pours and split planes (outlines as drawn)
no net on Top Layer "Top-No Net" (hatched 90Degree grid 0.1 track 0.15, remove dead copper, pour order 148): 17 vertices, not listed, extent 15.03,61.35 24.03,86.89
no net on Top Layer "Solder Mask Bottom-No Net" (hatched 90Degree grid 0.1 track 0.15, remove dead copper, pour order 110): 109 vertices, not listed, extent 1.49,1.28 191.06,31.9
no net on Top Layer "Top-No Net" (hatched 90Degree grid 0.1 track 0.15, remove dead copper, pour order 114): 187.55,70.93 188.06,70.42 188.06,60.34 187.72,60 179.47,60 179.06,60.41 179.06,65.23 180.98,67.15 180.98,70.42 181.49,70.93
no net on Top Layer "Top-No Net" (hatched 90Degree grid 0.1 track 0.15, remove dead copper, pour order 155): 17 vertices, not listed, extent 164.295,66.89 173.067,86.73
no net on Top Layer "Top-No Net" (hatched 90Degree grid 0.1 track 0.15, remove dead copper, pour order 154): 79 vertices, not listed, extent 0.42,45.42 193.61,90.72
no net on Top Layer "Top-No Net" (hatched 90Degree grid 0.1 track 0.15, remove dead copper, pour order 123): 22 vertices, not listed, extent 1.42,17.94 7,75.73
no net on Top Layer "Top-No Net" (hatched 90Degree grid 0.1 track 0.15, remove dead copper, pour order 133): 138.88,33.5 141.7,33.5 142.09,33.11 142.09,21.4 141.93,21.24 138.7,21.24 138.44,21.5 138.44,33.06
no net on Top Layer "Top-No Net" (hatched 90Degree grid 0.1 track 0.15, remove dead copper, pour order 134): 73.88,33.5 76.7,33.5 77.09,33.11 77.09,21.4 76.93,21.24 73.7,21.24 73.44,21.5 73.44,33.06
no net on Top Layer "Top-No Net" (hatched 90Degree grid 0.1 track 0.15, remove dead copper, pour order 135): 8.88,33.5 11.7,33.5 12.09,33.11 12.09,21.4 11.93,21.24 8.7,21.24 8.44,21.5 8.44,33.06
no net on Top Layer "Top-No Net" (hatched 90Degree grid 0.1 track 0.15, remove dead copper, pour order 159): 175.5,86.71 185.86,86.71 186.96,85.61 186.96,80.91 188.03,79.84 188.03,72.78 187.42,72.17 182.25,72.17 179.57,74.85 175.71,74.85 174.75,75.81 174.75,85.96
no net on Top Layer "Top-No Net" (hatched 90Degree grid 0.1 track 0.15, remove dead copper, pour order 198): 18 vertices, not listed, extent 160.03,11.33 167.9,17.98
no net on Top Layer "Top-No Net" (hatched 90Degree grid 0.1 track 0.15, remove dead copper, pour order 124): 16.86,31.23 18.53,31.23 18.71,31.05 18.71,29.32 18.59,29.2 16.85,29.2 16.69,29.36 16.69,31.06
no net on Top Layer "Top-No Net" (hatched 90Degree grid 0.1 track 0.15, remove dead copper, pour order 199): 18 vertices, not listed, extent 95.03,11.33 102.9,17.98
no net on Top Layer "Top-No Net" (hatched 90Degree grid 0.1 track 0.15, remove dead copper, pour order 194): 176.54,44.86 176.92,44.48 176.92,41.02 176.57,40.67 173.57,40.67 173.07,41.17 173.07,44.41 173.52,44.86
no net on Top Layer "Top-No Net" (hatched 90Degree grid 0.1 track 0.15, remove dead copper, pour order 195): 111.54,44.86 111.92,44.48 111.92,41.02 111.57,40.67 108.57,40.67 108.07,41.17 108.07,44.41 108.52,44.86
no net on Top Layer "Top-No Net" (hatched 90Degree grid 0.1 track 0.15, remove dead copper, pour order 196): 46.54,44.86 46.92,44.48 46.92,41.02 46.57,40.67 43.57,40.67 43.07,41.17 43.07,44.41 43.52,44.86
no net on Top Layer "Top-No Net" (hatched 90Degree grid 0.1 track 0.15, remove dead copper, pour order 145): 173.3,31.59 177.2,31.59 177.8,30.99 177.8,26.86 176.4,25.46 172.9,25.46 172.33,26.03 172.33,30.62
no net on Top Layer "Top-No Net" (hatched 90Degree grid 0.1 track 0.15, remove dead copper, pour order 161): 45.92,86.71 57.1,86.71 58.03,85.78 58.03,71.63 57.38,70.98 52.99,70.98 52.3,71.67 52.3,73.29 50.74,74.85 46.16,74.85 45.09,75.92 45.09,85.88
no net on Top Layer "Top-No Net" (hatched 90Degree grid 0.1 track 0.15, remove dead copper, pour order 132): 26.59,82.72 33.21,82.72 33.87,82.06 33.87,70.17 33.22,69.52 26.83,69.52 25.85,70.5 25.85,81.98
no net on Top Layer "Top-No Net" (hatched 90Degree grid 0.1 track 0.15, remove dead copper, pour order 157): 17 vertices, not listed, extent 34.67,66.89 44.04,86.73
no net on Top Layer "Top-No Net" (hatched 90Degree grid 0.1 track 0.15, remove dead copper, pour order 126): 146.86,31.23 148.53,31.23 148.71,31.05 148.71,29.32 148.59,29.2 146.85,29.2 146.69,29.36 146.69,31.06
no net on Top Layer "Top-No Net" (hatched 90Degree grid 0.1 track 0.15, remove dead copper, pour order 125): 81.86,31.23 83.53,31.23 83.71,31.05 83.71,29.32 83.59,29.2 81.85,29.2 81.69,29.36 81.69,31.06
no net on Top Layer "Top-No Net" (hatched 90Degree grid 0.1 track 0.15, remove dead copper, pour order 150): 17 vertices, not listed, extent 145.03,61.35 153.87,86.89
no net on Top Layer "Top-No Net" (hatched 90Degree grid 0.1 track 0.15, remove dead copper, pour order 149): 17 vertices, not listed, extent 80.03,61.35 88.87,86.89
no net on Top Layer "Top-No Net" (hatched 90Degree grid 0.1 track 0.15, remove dead copper, pour order 141): 156.41,64.95 161.22,64.95 161.48,64.69 161.48,59.39 161.17,59.08 156.46,59.08 156.21,59.33 156.21,64.75 156.41,64.95
no net on Top Layer "Top-No Net" (hatched 90Degree grid 0.1 track 0.15, remove dead copper, pour order 140): 91.41,64.95 96.22,64.95 96.48,64.69 96.48,59.39 96.17,59.08 91.46,59.08 91.21,59.33 91.21,64.75 91.41,64.95
no net on Top Layer "Top-No Net" (hatched 90Degree grid 0.1 track 0.15, remove dead copper, pour order 143): 47.05,73.14 51.16,73.14 51.6,72.7 51.6,67.29 51.34,67.03 46.92,67.03 46.67,67.28 46.67,72.76
no net on Top Layer "Top-No Net" (hatched 90Degree grid 0.1 track 0.15, remove dead copper, pour order 139): 26.41,64.95 31.22,64.95 31.48,64.69 31.48,59.39 31.17,59.08 26.46,59.08 26.21,59.33 26.21,64.75 26.41,64.95
no net on Top Layer "Top-No Net" (hatched 90Degree grid 0.1 track 0.15, remove dead copper, pour order 171): 53.01,69.42 57.34,69.42 57.99,68.77 57.99,61.11 57.42,60.54 50.21,60.54 49.7,61.05 49.7,65.35 50.56,66.21 51.58,66.21 52.33,66.96 52.33,68.74
no net on Top Layer "Top-No Net" (hatched 90Degree grid 0.1 track 0.15, remove dead copper, pour order 142): 176.2,73.14 179.95,73.14 180.29,72.8 180.29,67.39 179.93,67.03 176.07,67.03 175.82,67.28 175.82,72.76
no net on Top Layer "Top-No Net" (hatched 90Degree grid 0.1 track 0.15, remove dead copper, pour order 138): 69.19,48.82 70.86,48.82 71.17,49.13 71.17,50.34 71.51,50.68 73.63,50.68 73.63,47.45 73.37,47.19 69.12,47.19 68.94,47.37 68.94,48.57
no net on Top Layer "Top-No Net" (hatched 90Degree grid 0.1 track 0.15, remove dead copper, pour order 136): 134.19,48.82 135.86,48.82 136.17,49.13 136.17,50.34 136.51,50.68 138.63,50.68 138.63,47.45 138.37,47.19 134.12,47.19 133.94,47.37 133.94,48.57
no net on Top Layer "Top-No Net" (hatched 90Degree grid 0.1 track 0.15, remove dead copper, pour order 172): 118.01,69.42 122.34,69.42 122.99,68.77 122.99,62.13 122.52,61.66 117.77,61.66 117.33,62.1 117.33,68.74
no net on Top Layer "Top-No Net" (hatched 90Degree grid 0.1 track 0.15, remove dead copper, pour order 127): 90.62,82.72 98.07,82.72 98.87,81.92 98.87,70.17 98.22,69.52 91.83,69.52 89.96,71.39 89.96,82.06
no net on Top Layer "Top-No Net" (hatched 90Degree grid 0.1 track 0.15, remove dead copper, pour order 158): 17 vertices, not listed, extent 99.84,67.69 109.04,86.73
no net on Top Layer "Top-No Net" (hatched 90Degree grid 0.1 track 0.15, remove dead copper, pour order 128): 155.61,82.72 162.7,82.72 163.36,82.06 163.36,70.21 162.67,69.52 156.83,69.52 154.96,71.39 154.96,82.07
no net on Top Layer "Top-No Net" (hatched 90Degree grid 0.1 track 0.15, remove dead copper, pour order 137): 5.1,48.824 6.77,48.824 7.08,49.134 7.08,50.344 7.42,50.684 9.54,50.684 9.54,47.454 9.28,47.194 5.03,47.194 4.85,47.374 4.85,48.574
no net on Top Layer "Top-No Net" (hatched 90Degree grid 0.1 track 0.15, remove dead copper, pour order 200): 18 vertices, not listed, extent 30.03,11.33 37.9,17.98
no net on Top Layer "Top-No Net" (hatched 90Degree grid 0.1 track 0.15, remove dead copper, pour order 144): 111.93,73.15 116.15,73.15 116.6,72.7 116.6,61.58 115.68,60.66 112.05,60.66 111.67,61.04 111.67,72.89
no net on Top Layer "Top-No Net" (hatched 90Degree grid 0.1 track 0.15, remove dead copper, pour order 162): 111.97,86.71 121.64,86.71 123.03,85.32 123.03,71.63 122.38,70.98 117.99,70.98 117.3,71.67 117.3,74.95 116.66,75.59 111.83,75.59 110.92,76.5 110.92,85.66
no net on Top Layer "Top-No Net" (hatched 90Degree grid 0.1 track 0.15, remove dead copper, pour order 147): 43.12,31.59 47.2,31.59 47.8,30.99 47.8,26.58 46.48,25.26 43.01,25.26 42.33,25.94 42.33,30.8
no net on Top Layer "Top-No Net" (hatched 90Degree grid 0.1 track 0.15, remove dead copper, pour order 146): 108.3,31.59 112.2,31.59 112.8,30.99 112.8,26.6 111.66,25.46 107.9,25.46 107.33,26.03 107.33,30.62
no net on Top Layer "Solder Mask Bottom-No Net" (hatched 90Degree grid 0.1 track 0.15, remove dead copper, pour order 113): 72.31,7.125 74.29,7.125 74.79,6.625 79.22,2.195 79.22,2.08 67.97,2.08 67.955,2.065 66.972,2.065 66.895,2.142 71.878,7.125 72.22,7.125
no net on Top Layer "Solder Mask Bottom-No Net" (hatched 90Degree grid 0.1 track 0.15, remove dead copper, pour order 112): 140.345,7.125 145.39,2.08 132.91,2.08 132.895,2.065 131.912,2.065 131.835,2.142 136.818,7.125
no net on Top Layer "Top-No Net" (hatched 90Degree grid 0.1 track 0.15, remove dead copper, pour order 197): 29 vertices, not listed, extent 0.43,0.42 145.425,36.27
no net on Top Layer "Top-No Net" (hatched 90Degree grid 0.1 track 0.15, remove dead copper, pour order 122): 65.68,75.73 68.69,75.73 69.13,75.29 69.13,60.965 68.612,60.447 65.755,60.455 65.189,61.021 65.17,75.22
no net on Top Layer "Top-No Net" (hatched 90Degree grid 0.1 track 0.15, remove dead copper, pour order 152): 70.885,86.75 76.54,86.75 77.2,86.09 77.2,63.58 76.42,62.8 70.825,62.8 70.05,63.575 70.05,85.915
no net on Top Layer "Top-No Net" (hatched 90Degree grid 0.1 track 0.15, remove dead copper, pour order 121): 130.68,75.73 133.7,75.73 134.165,75.265 134.165,61.085 133.527,60.447 130.755,60.455 130.189,61.021 130.17,75.22
no net on Top Layer "Top-No Net" (hatched 90Degree grid 0.1 track 0.15, remove dead copper, pour order 153): 135.635,86.75 141.54,86.75 142.2,86.09 142.2,63.58 141.42,62.8 135.75,62.8 134.995,63.555 134.995,86.11
no net on Top Layer "Top-No Net" (hatched 90Degree grid 0.1 track 0.15, remove dead copper, pour order 151): 9.838,86.748 12.49,86.748 13.485,85.753 13.485,63.23 13.053,62.798 8.352,62.798 7.76,63.39 7.76,84.67
no net on Top Layer "Top-No Net" (hatched 90Degree grid 0.1 track 0.15, remove dead copper, pour order 165): 17 vertices, not listed, extent 43.02,40.62 62.46,57.7
no net on Top Layer "Top-No Net" (hatched 90Degree grid 0.1 track 0.15, remove dead copper, pour order 164): 17 vertices, not listed, extent 108.02,40.62 127.46,57.7
no net on Top Layer "Top-No Net" (hatched 90Degree grid 0.1 track 0.15, remove dead copper, pour order 163): 17 vertices, not listed, extent 173.02,40.62 192.46,57.7
NewNet on Top Layer "Top-No Net" (hatched 90Degree grid 0.1 track 0.15, pour order 175): 40.22,22.94 45.33,22.94 49.68,27.285 52.009,29.607 58.76,29.6 59.22,29.14 59.22,6.29 58.23,5.3 40.33,5.3 39.47,6.16 39.47,22.19
no net on Top Layer "Top-No Net" (hatched 90Degree grid 0.1 track 0.15, pour order 174): 105.22,22.94 110.33,22.94 114.68,27.285 117.009,29.607 123.76,29.6 124.22,29.14 124.22,6.29 123.23,5.3 105.33,5.3 104.47,6.16 104.47,22.19
no net on Top Layer "Top-No Net" (hatched 90Degree grid 0.1 track 0.15, pour order 173): 170.22,22.94 175.33,22.94 179.68,27.285 182.009,29.607 188.76,29.6 189.22,29.14 189.22,6.29 188.23,5.3 170.33,5.3 169.47,6.16 169.47,22.19
no net on Bottom Layer "Top-No Net" (hatched 90Degree grid 0.1 track 0.15, remove dead copper, pour order 191): 27 vertices, not listed, extent 0.29,0.3 165.92,44.69
no net on Bottom Layer "Top-No Net" (hatched 90Degree grid 0.1 track 0.15, remove dead copper, pour order 116): 6.02,14.76 6.26,14.52 6.26,6.156 6.067,5.963 4.697,5.963 4.53,6.13 4.53,9.92 1.29,13.16 1.29,14.25 1.8,14.76
no net on Bottom Layer "Top-No Net" (hatched 90Degree grid 0.1 track 0.15, remove dead copper, pour order 115): 5.55,26.68 5.89,26.34 5.89,18.284 5.406,17.8 1.948,17.8 1.29,18.458 1.29,21.82 3.66,24.19 3.66,26.5 3.84,26.68
no net on Bottom Layer "Top-No Net" (hatched 90Degree grid 0.1 track 0.15, remove dead copper, pour order 203): 190.59,10.28 191.71,11.4 193.45,11.4 193.68,11.17 193.68,2.01 191.96,0.29 155.46,0.29 154.92,0.83 154.92,9.02 156.18,10.28
no net on Bottom Layer "Top-No Net" (hatched 90Degree grid 0.1 track 0.15, remove dead copper, pour order 201): 98.41,86.62 98.82,86.21 98.82,83.88 98.4,83.46 90.38,83.46 89.93,83.91 89.93,86.21 90.34,86.62
no net on Bottom Layer "Top-No Net" (hatched 90Degree grid 0.1 track 0.15, remove dead copper, pour order 192): 27 vertices, not listed, extent 124.15,45.46 180.67,86.36
no net on Bottom Layer "Top-No Net" (hatched 90Degree grid 0.1 track 0.15, remove dead copper, pour order 129): 21 vertices, not listed, extent 104.67,11.74 131.32,69.64
no net on Bottom Layer "Top-No Net" (hatched 90Degree grid 0.1 track 0.15, remove dead copper, pour order 130): 21 vertices, not listed, extent 39.67,11.74 66.32,69.64
no net on Bottom Layer "Top-No Net" (hatched 90Degree grid 0.1 track 0.15, remove dead copper, pour order 167): 172.71,32.13 177.51,32.13 177.87,31.77 177.87,25.92 177.39,25.44 172.61,25.44 172.24,25.81 172.24,31.66
no net on Bottom Layer "Top-No Net" (hatched 90Degree grid 0.1 track 0.15, remove dead copper, pour order 168): 107.71,32.13 112.51,32.13 112.87,31.77 112.87,25.92 112.39,25.44 107.61,25.44 107.24,25.81 107.24,31.66
no net on Bottom Layer "Top-No Net" (hatched 90Degree grid 0.1 track 0.15, remove dead copper, pour order 169): 42.71,32.13 47.51,32.13 47.87,31.77 47.87,25.92 47.39,25.44 42.61,25.44 42.24,25.81 42.24,31.66
no net on Bottom Layer "Top-No Net" (hatched 90Degree grid 0.1 track 0.15, remove dead copper, pour order 156): 35.37,86.43 43.31,86.43 44.04,85.7 44.04,70.01 43.38,69.35 35.3,69.35 34.67,69.98 34.67,85.73
no net on Bottom Layer "Top-No Net" (hatched 90Degree grid 0.1 track 0.15, remove dead copper, pour order 178): 144.92,90.59 152.69,90.59 153.87,89.41 153.87,61.71 153.51,61.35 144.74,61.35 143.73,62.36 143.73,89.4
no net on Bottom Layer "Top-No Net" (hatched 90Degree grid 0.1 track 0.15, remove dead copper, pour order 189): 135.95,90.52 141.66,90.52 142.71,89.47 142.71,64.09 141.42,62.8 135.69,62.8 134.9,63.59 134.9,89.47
no net on Bottom Layer "Top-No Net" (hatched 90Degree grid 0.1 track 0.15, remove dead copper, pour order 177): 15.94,86.31 23.41,86.31 24.02,85.7 24.02,61.77 23.6,61.35 15.83,61.35 15.3,61.88 15.3,85.67
no net on Bottom Layer "Top-No Net" (hatched 90Degree grid 0.1 track 0.15, remove dead copper, pour order 131): 26.59,82.72 33.21,82.72 33.87,82.06 33.87,70.17 33.22,69.52 26.83,69.52 25.85,70.5 25.85,81.98
no net on Bottom Layer "Top-No Net" (hatched 90Degree grid 0.1 track 0.15, remove dead copper, pour order 176): 79.47,86.31 88.18,86.31 88.87,85.62 88.87,61.71 88.51,61.35 79.74,61.35 78.73,62.36 78.73,85.57
no net on Bottom Layer "Top-No Net" (hatched 90Degree grid 0.1 track 0.15, remove dead copper, pour order 188): 70.72,86.28 76.88,86.28 77.71,85.45 77.71,64.09 76.42,62.8 70.69,62.8 69.9,63.59 69.9,85.46
no net on Bottom Layer "Top-No Net" (hatched 90Degree grid 0.1 track 0.15, remove dead copper, pour order 179): 172.55,45.87 177.33,45.87 177.79,45.41 177.79,39.85 177.28,39.34 172.58,39.34 172.17,39.75 172.17,45.49 172.55,45.87
no net on Bottom Layer "Top-No Net" (hatched 90Degree grid 0.1 track 0.15, remove dead copper, pour order 170): 107.55,45.87 112.33,45.87 112.79,45.41 112.79,39.85 112.28,39.34 107.58,39.34 107.17,39.75 107.17,45.49 107.55,45.87
no net on Bottom Layer "Top-No Net" (hatched 90Degree grid 0.1 track 0.15, remove dead copper, pour order 166): 42.55,45.87 47.33,45.87 47.79,45.41 47.79,39.85 47.28,39.34 42.58,39.34 42.17,39.75 42.17,45.49 42.55,45.87
no net on Bottom Layer "Top-No Net" (hatched 90Degree grid 0.1 track 0.15, remove dead copper, pour order 119): 180.62,56.53 188.34,48.81 188.34,41.15 187.85,40.66 180.21,40.66 178.66,42.21 178.66,46.1 177.66,47.1 172.74,47.1 172.16,47.68 172.16,55.9 172.79,56.53
no net on Bottom Layer "Top-No Net" (hatched 90Degree grid 0.1 track 0.15, remove dead copper, pour order 118): 115.62,56.53 123.34,48.81 123.34,41.15 122.85,40.66 115.21,40.66 113.66,42.21 113.66,46.1 112.66,47.1 107.74,47.1 107.16,47.68 107.16,55.9 107.79,56.53
no net on Bottom Layer "Top-No Net" (hatched 90Degree grid 0.1 track 0.15, remove dead copper, pour order 117): 50.62,56.53 58.34,48.81 58.34,41.15 57.85,40.66 50.21,40.66 48.66,42.21 48.66,46.1 47.66,47.1 42.74,47.1 42.16,47.68 42.16,55.9 42.79,56.53
no net on Bottom Layer "Top-No Net" (hatched 90Degree grid 0.1 track 0.15, remove dead copper, pour order 160): 45.75,86.41 57.21,86.41 58.03,85.59 58.03,71.63 57.38,70.98 52.99,70.98 52.3,71.67 52.3,73.29 50.74,74.85 46.11,74.85 45.09,75.87 45.09,85.75
no net on Bottom Layer "Top-No Net" (hatched 90Degree grid 0.1 track 0.15, remove dead copper, pour order 186): 112.02,86.43 121.8,86.43 123.03,85.2 123.03,71.63 122.38,70.98 117.99,70.98 117.3,71.67 117.3,73.49 116.48,74.31 112.73,74.31 111.09,75.95 111.09,85.5
no net on Bottom Layer "Top-No Net" (hatched 90Degree grid 0.1 track 0.15, remove dead copper, pour order 120): 23 vertices, not listed, extent 170.54,10.89 193.53,63.02
no net on Bottom Layer "Top-No Net" (hatched 90Degree grid 0.1 track 0.15, remove dead copper, pour order 202): 33.27,86.51 33.67,86.11 33.67,83.91 33.11,83.35 26.43,83.35 25.9,83.88 25.9,86.11 26.3,86.51
no net on Bottom Layer "Top-No Net" (hatched 90Degree grid 0.1 track 0.15, remove dead copper, pour order 183): 100.26,86.57 107.89,86.57 109.04,85.42 109.04,70.73 107.86,69.55 100.76,69.55 99.79,70.52 99.79,86.1
no net on Bottom Layer "Top-No Net" (hatched 90Degree grid 0.1 track 0.15, remove dead copper, pour order 184): 9.93,86.136 13.114,86.136 13.41,85.84 13.41,63.176 13,62.766 10,62.766 9.13,63.636 9.13,85.336
no net on Bottom Layer "Top-No Net" (hatched 90Degree grid 0.1 track 0.15, remove dead copper, pour order 180): 90.61,82.72 98.04,82.72 98.87,81.89 98.87,70.17 98.22,69.52 91.7,69.52 89.96,71.26 89.96,82.07
no net on Bottom Layer "Top-No Net" (hatched 90Degree grid 0.1 track 0.15, remove dead copper, pour order 193): 27 vertices, not listed, extent 59.15,45.45 116.698,86.36
no net on Bottom Layer "Top-No Net" (hatched 90Degree grid 0.1 track 0.15, remove dead copper, pour order 181): 155.61,82.72 163.16,82.72 163.87,82.01 163.87,67.61 163.14,66.88 157.02,66.88 156.29,67.61 156.29,70.1 154.96,71.43 154.96,82.07
no net on Bottom Layer "Top-No Net" (hatched 90Degree grid 0.1 track 0.15, remove dead copper, pour order 187): 29 vertices, not listed, extent 2.29,61.38 134.167,90.62
no net on Bottom Layer "Top-No Net" (hatched 90Degree grid 0.1 track 0.15, remove dead copper, pour order 111): 29 vertices, not listed, extent 0.425,45.4 51.7,83.42
no net on Bottom Layer "Top-No Net" (hatched 90Degree grid 0.1 track 0.15, remove dead copper, pour order 190): 19 vertices, not listed, extent 154.8,57.57 193.48,90.57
